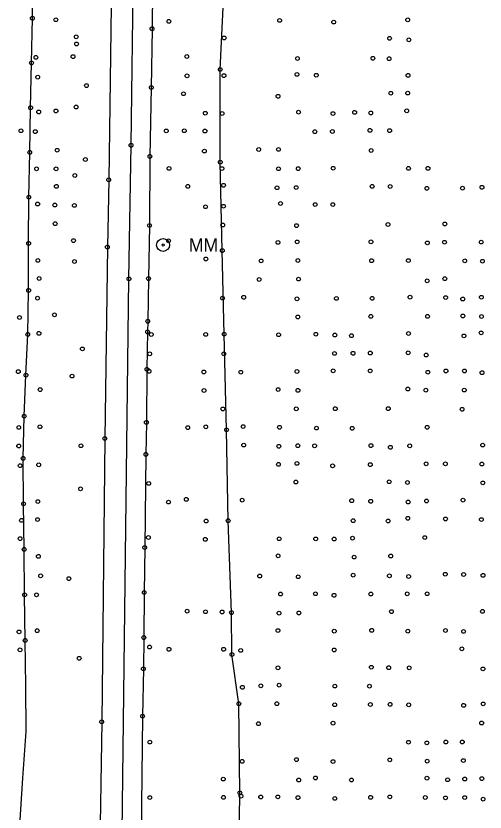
# Model space of a CAD drawing. Extents: x 20503438 to 20508873, y 7964251 to 7984667.
# Drawn here: x 20506616.9 to 20506866.4, y 7966287.3 to 7966710.9 of the extents above; entities that cross this region are included whole.
import ezdxf

# ---------------------------------------------------------------- set-up
doc = ezdxf.new("R2010")
doc.units = 0
for name, color, linetype in [('SurBreakLine', 7, 'Continuous'), ('SurConcreteSlab', 7, 'Continuous'), ('SurDrainageArrowDown', 7, 'Continuous'), ('SurDrainageArrowUp', 7, 'Continuous'), ('SurEdgeRoadPaved', 7, 'Continuous'), ('SurRoadPoints', 7, 'Continuous'), ('SurSurveyPoints', 7, 'Continuous')]:
    doc.layers.add(name, color=color, linetype=linetype)

msp = doc.modelspace()

# ---------------------------------------------------------------- linework, layer by layer
at = {"layer": 'SurBreakLine'}
msp.add_lwpolyline([(20506676.27, 7967436.58), (20506673.75, 7967260.63), (20506673.38, 7967229.74), (20506672.93, 7967188.92), (20506672.41, 7967153.72), (20506672.19, 7967124.04), (20506671.1, 7967048.34), (20506670.26, 7966945.33), (20506669.67, 7966906.46), (20506669.41, 7966871.04), (20506668.85, 7966836.8), (20506668.54, 7966801.73), (20506668.02, 7966767.22), (20506667.76, 7966729.81), (20506666.24, 7966623.69), (20506665.51, 7966587.93), (20506664.19, 7966486.04), (20506662.51, 7966335.32), (20506661.23, 7966248.03), (20506660.03, 7966157.63), (20506658.3, 7966009.76)], dxfattribs=at)
at = {"layer": 'SurConcreteSlab'}
msp.add_lwpolyline([(20506689.7, 7966746.61), (20506689.28, 7966704.08), (20506688.88, 7966672.82), (20506688.14, 7966636.15), (20506687.92, 7966599.43), (20506687.39, 7966571.12), (20506686.99, 7966548.42), (20506686.9, 7966542.73), (20506686.59, 7966522.86), (20506686.25, 7966494.65), (20506686.03, 7966477.61), (20506685.38, 7966428.04), (20506685.13, 7966404.1), (20506684.93, 7966380.11), (20506684.65, 7966363.47), (20506684.25, 7966338.35), (20506682.89, 7966227.64), (20506681.53, 7966131.86)], dxfattribs=at)
at = {"layer": 'SurDrainageArrowDown'}
msp.add_lwpolyline([(20506616.88, 7966180.41), (20506617.4, 7966205.4), (20506617.92, 7966230.4), (20506618.45, 7966255.39), (20506618.97, 7966280.39), (20506620.54, 7966305.33), (20506622.35, 7966330.27), (20506622.07, 7966354.47), (20506621.79, 7966378.67), (20506621.52, 7966402.88), (20506621.24, 7966427.08), (20506620.96, 7966451.29), (20506620.68, 7966475.49), (20506621.28, 7966497.96), (20506622.23, 7966519.72), (20506623.18, 7966541.47), (20506623.65, 7966564.87), (20506623.65, 7966589.87), (20506623.79, 7966614.5), (20506624.24, 7966638.28), (20506624.7, 7966662.06), (20506625.16, 7966685.84), (20506625.61, 7966709.62), (20506625.94, 7966733.94)], dxfattribs=at)
at = {"layer": 'SurDrainageArrowUp'}
msp.add_lwpolyline([(20506748.37, 7966102.43), (20506739.98, 7966120.94), (20506735.03, 7966132), (20506735.65, 7966158.21), (20506738.35, 7966207.5), (20506735.41, 7966256.62), (20506736, 7966297.52), (20506735.47, 7966344.97), (20506731.78, 7966371.15), (20506731.51, 7966393.42), (20506729.75, 7966442.32), (20506728.92, 7966490.67), (20506727.65, 7966541.52), (20506726.65, 7966586.02), (20506725.58, 7966633.07), (20506725.56, 7966682.41), (20506728.02, 7966733.71)], dxfattribs=at)
at = {"layer": 'SurEdgeRoadPaved'}
msp.add_lwpolyline([(20506671.44, 7966131.99), (20506673.27, 7966261.84), (20506677.01, 7966570.96), (20506678.1, 7966642.03), (20506680.7, 7966833.13), (20506681.3, 7966886.9), (20506681.36, 7966892.52), (20506681.4, 7966895.33), (20506681.63, 7966918.21), (20506682.1, 7966969.83), (20506684.74, 7967192.21), (20506685.18, 7967235.97), (20506685.47, 7967264.79), (20506686.29, 7967317.73), (20506686.56, 7967334.59), (20506686.95, 7967373.78)], dxfattribs=at)
at = {"layer": 'SurRoadPoints'}
for radius in [3.43, 0.571]:
    msp.add_circle((20506695.16, 7966588.99), radius, dxfattribs=at)
at = {"layer": 'SurSurveyPoints'}
for centre in [(20506625.61, 7966709.62), (20506638.1, 7966708.83), (20506757.15, 7966708.48), (20506825.26, 7966708.81), (20506689.28, 7966704.08), (20506698.26, 7966707.98), (20506785.91, 7966707.6), (20506648.97, 7966699.76), (20506649.15, 7966695.97), (20506727.64, 7966699.16), (20506815.62, 7966698.95), (20506825.9, 7966698.17), (20506627.51, 7966688.83), (20506647.26, 7966689.2), (20506707.77, 7966689.27), (20506766.6, 7966688.2), (20506806.76, 7966688.32), (20506815.37, 7966688.11), (20506625.16, 7966685.84), (20506707.89, 7966679.02), (20506725.56, 7966682.41), (20506727.53, 7966679.11), (20506766.36, 7966679.76), (20506776.65, 7966679.32), (20506825.44, 7966679.26), (20506628.47, 7966678.28), (20506654.38, 7966673.8), (20506688.88, 7966672.82), (20506706.02, 7966669.47), (20506756.28, 7966668.12), (20506816.25, 7966669.74), (20506825.27, 7966669.83), (20506624.7, 7966662.06), (20506648.87, 7966662.39), (20506628.99, 7966659.78), (20506638.19, 7966660.3), (20506717.61, 7966659.09), (20506726.62, 7966658.97), (20506767.21, 7966659.68), (20506785.5, 7966658.92), (20506797.05, 7966659.55), (20506805.61, 7966659.26), (20506824.73, 7966660.39), (20506619.57, 7966649.77), (20506627.17, 7966649.32), (20506696.85, 7966649.7), (20506706.45, 7966649.78), (20506717.44, 7966649.63), (20506775.89, 7966649.28), (20506785.18, 7966649.39), (20506805.2, 7966649.99), (20506815.67, 7966649.84), (20506678.1, 7966642.03), (20506624.24, 7966638.28), (20506638.82, 7966639.42), (20506717.11, 7966638.95), (20506746.01, 7966639.83), (20506756.53, 7966639.84), (20506805.8, 7966639.27), (20506653.82, 7966634.5), (20506688.14, 7966636.15), (20506725.58, 7966633.07), (20506627.87, 7966629.52), (20506638.23, 7966629.54), (20506698.33, 7966629.73), (20506726.46, 7966629.66), (20506756.56, 7966629.57), (20506767.04, 7966629.64), (20506785.6, 7966629.83), (20506825.68, 7966629.78), (20506836.04, 7966629.77), (20506648.22, 7966625.98), (20506666.24, 7966623.69), (20506638.39, 7966620.18), (20506708.28, 7966620.18), (20506727.32, 7966620.78), (20506755.75, 7966619.46), (20506765.93, 7966619.54), (20506806.34, 7966620.18), (20506815.96, 7966620.12), (20506864.78, 7966619.71), (20506835.49, 7966619.15), (20506854.42, 7966619.22), (20506623.79, 7966614.5), (20506757.6, 7966611.08), (20506628.43, 7966610.79), (20506637.55, 7966610.28), (20506647.95, 7966610.05), (20506717.76, 7966609.36), (20506727.33, 7966609.62), (20506776.06, 7966610.51), (20506785.43, 7966610.52), (20506637.77, 7966600.32), (20506687.92, 7966599.43), (20506726.89, 7966599.61), (20506766.16, 7966599.31), (20506814.76, 7966599.93), (20506845, 7966600.2), (20506623.65, 7966589.87), (20506647.48, 7966591.34), (20506698.06, 7966591.2), (20506756.27, 7966590.36), (20506766.45, 7966590.66), (20506805.74, 7966590.71), (20506835.74, 7966590.11), (20506844.83, 7966590.48), (20506864.38, 7966590.55), (20506665.51, 7966587.93), (20506726.65, 7966586.02), (20506717.92, 7966581.59), (20506628.57, 7966580.8), (20506647.99, 7966580.23), (20506747.27, 7966580.54), (20506766.86, 7966580.75), (20506806.07, 7966580.64), (20506825.63, 7966580.73), (20506855.61, 7966580.56), (20506865.01, 7966580.35), (20506629.19, 7966571.18), (20506677.01, 7966570.96), (20506687.39, 7966571.12), (20506746.25, 7966570.67), (20506767.22, 7966570.86), (20506835.65, 7966569.96), (20506845.01, 7966571.07), (20506623.65, 7966564.87), (20506628.39, 7966560.74), (20506726.79, 7966560.76), (20506738.03, 7966561.17), (20506766.37, 7966560.34), (20506787.33, 7966560.57), (20506806.33, 7966560.63), (20506826.49, 7966561.25), (20506845.46, 7966561.03), (20506854.53, 7966560.25), (20506864.44, 7966561.2), (20506637.37, 7966551.83), (20506618.77, 7966550.44), (20506686.99, 7966548.42), (20506766.8, 7966550.73), (20506805.66, 7966551.02), (20506835.83, 7966551.02), (20506854.58, 7966551.24), (20506864.57, 7966550.95), (20506623.18, 7966541.47), (20506629.14, 7966541.98), (20506686.9, 7966542.73), (20506688.9, 7966541.37), (20506717.82, 7966541.43), (20506727.65, 7966541.52), (20506756.62, 7966541.25), (20506776.44, 7966541.52), (20506786.5, 7966541.1), (20506795.34, 7966540.74), (20506825.7, 7966541.91), (20506855.19, 7966540.65), (20506864.35, 7966542.24), (20506652.22, 7966533.72), (20506688.05, 7966531.11), (20506727.47, 7966531.09), (20506786.35, 7966531.31), (20506796.2, 7966531.4), (20506805.36, 7966531.53), (20506825.5, 7966531.65), (20506835.13, 7966530.47), (20506686.59, 7966522.86), (20506785.6, 7966522.04), (20506805.28, 7966522.03), (20506845.63, 7966521.98), (20506855.45, 7966522), (20506618.15, 7966521.63), (20506622.23, 7966519.72), (20506646.74, 7966519.25), (20506687.7, 7966521.8), (20506716.84, 7966521.46), (20506736.48, 7966521.32), (20506766.35, 7966521.69), (20506835.97, 7966521.3), (20506864.81, 7966521.08), (20506629.79, 7966512.05), (20506716.92, 7966511.62), (20506756.34, 7966512.1), (20506766.9, 7966511.66), (20506825.32, 7966512.39), (20506834.89, 7966511.78), (20506855.38, 7966511.82), (20506726.93, 7966501.78), (20506766.02, 7966501.84), (20506786.75, 7966501.92), (20506814.95, 7966501.96), (20506854.21, 7966501.59), (20506621.28, 7966497.96), (20506629.67, 7966492.32), (20506686.25, 7966494.65), (20506717.84, 7966492.26), (20506737.71, 7966492.41), (20506618.39, 7966491.94), (20506708.28, 7966491.83), (20506728.92, 7966490.67), (20506757.07, 7966492.01), (20506776.71, 7966491.59), (20506795.77, 7966491.5), (20506835.64, 7966492.01), (20506664.19, 7966486.04), (20506618.37, 7966482.07), (20506651.48, 7966482.21), (20506738.04, 7966482.56), (20506756.72, 7966481.9), (20506766.83, 7966482.24), (20506775.75, 7966482.15), (20506805.72, 7966482.26), (20506816.04, 7966481.37), (20506826.33, 7966482.17), (20506865.14, 7966482.56), (20506620.68, 7966475.49), (20506686.03, 7966477.61), (20506619.11, 7966471.61), (20506628.98, 7966472.04), (20506756.49, 7966472.29), (20506766.37, 7966472.81), (20506785.35, 7966471.54), (20506805.38, 7966472.17), (20506835.06, 7966472.59), (20506845.3, 7966472.6), (20506864.68, 7966472.48), (20506765.8, 7966462.89), (20506815.43, 7966463.05), (20506825.12, 7966462.64), (20506651.26, 7966459.26), (20506687.51, 7966462.15), (20506865.25, 7966462.43), (20506620.96, 7966451.29), (20506628.57, 7966452.52), (20506698.05, 7966452.22), (20506707.49, 7966453.69), (20506737.26, 7966453.25), (20506795.49, 7966452.97), (20506805.57, 7966452.65), (20506825.53, 7966452.25), (20506835.29, 7966452.81), (20506854.68, 7966453.24), (20506619.86, 7966442.52), (20506628.39, 7966442.92), (20506718.07, 7966442.15), (20506729.75, 7966442.32), (20506796.25, 7966442.34), (20506814.83, 7966442.17), (20506825.3, 7966443.62), (20506845.39, 7966443.25), (20506864.44, 7966442.92), (20506687.31, 7966433.38), (20506795.94, 7966433.03), (20506834.33, 7966433.34), (20506619.11, 7966432.79), (20506717.61, 7966432.4), (20506756.88, 7966432.72), (20506776.33, 7966432.64), (20506786.15, 7966432.58), (20506621.24, 7966427.08), (20506685.38, 7966428.04), (20506628.83, 7966423.35), (20506756.32, 7966423.63), (20506796.75, 7966422.96), (20506816.23, 7966423.52), (20506630.03, 7966412.98), (20506746.54, 7966412.89), (20506767.04, 7966412.5), (20506796.27, 7966413.36), (20506815.51, 7966413.01), (20506825.75, 7966412.66), (20506845.26, 7966413.85), (20506855.03, 7966413.7), (20506865.32, 7966413.26), (20506645.05, 7966411.52), (20506685.13, 7966404.1), (20506757.66, 7966403.33), (20506776.19, 7966403.47), (20506805.66, 7966403.31), (20506825.02, 7966403.42), (20506835.59, 7966403.45), (20506621.52, 7966402.88), (20506627.86, 7966402.91), (20506786.08, 7966402.64), (20506707.91, 7966394.22), (20506717.71, 7966393.88), (20506726.55, 7966393.79), (20506731.51, 7966393.42), (20506756.83, 7966393.13), (20506767.4, 7966393.25), (20506816.61, 7966393.96), (20506865.02, 7966394.09), (20506618.54, 7966383.16), (20506628.22, 7966383.81), (20506756.26, 7966383.87), (20506786.21, 7966383.55), (20506806.11, 7966383.98), (20506825.29, 7966383.58), (20506845.32, 7966383.91), (20506854.97, 7966383.41), (20506621.79, 7966378.67), (20506684.93, 7966380.11), (20506619.05, 7966373.62), (20506687.97, 7966375.11), (20506698.29, 7966373.93), (20506727.37, 7966373.93), (20506854.09, 7966374.17), (20506731.78, 7966371.15), (20506736.44, 7966373.31), (20506786.2, 7966373.56), (20506650.53, 7966369.13), (20506684.65, 7966363.47), (20506756.26, 7966364.06), (20506805.92, 7966364.37), (20506815.16, 7966364.13), (20506826.07, 7966364.04), (20506865.29, 7966363.49), (20506737.32, 7966353.69), (20506747.17, 7966354.48), (20506756.86, 7966354.83), (20506786.49, 7966354.34), (20506804.9, 7966354.29), (20506735.47, 7966344.97), (20506755.64, 7966344.96), (20506786.44, 7966344.41), (20506805.4, 7966344.56), (20506815.91, 7966344.63), (20506825.79, 7966344.35), (20506855.01, 7966344.1), (20506865.42, 7966344.87), (20506684.25, 7966338.35), (20506662.51, 7966335.32), (20506745.88, 7966334.33), (20506785.56, 7966334.62), (20506864.59, 7966334.68), (20506688.13, 7966324.54), (20506825.69, 7966324.48), (20506835.46, 7966324.11), (20506845.53, 7966324.57), (20506854.32, 7966324.6), (20506766.07, 7966315.21), (20506815.73, 7966315.07), (20506835.67, 7966314.42), (20506854.89, 7966314.72), (20506737.19, 7966314.3), (20506785.55, 7966314.19), (20506727.18, 7966304.86), (20506767.29, 7966304.36), (20506776.18, 7966305.48), (20506795.32, 7966304.38), (20506835.5, 7966305.36), (20506846.5, 7966304.5), (20506855.57, 7966304.89), (20506864.69, 7966305.11), (20506736, 7966297.52), (20506688.09, 7966295.04), (20506727.25, 7966295.13), (20506736.6, 7966295.76), (20506747.06, 7966295.34), (20506756.2, 7966295.39), (20506766.91, 7966294.99), (20506786.53, 7966294.57), (20506805.54, 7966295.13), (20506815.77, 7966295.39), (20506834.61, 7966295.09), (20506845.35, 7966294.87), (20506855.58, 7966295.02), (20506865.36, 7966294.19)]:
    msp.add_circle(centre, 1, dxfattribs=at)

# ---------------------------------------------------------------- texts
at = {"layer": 'SurRoadPoints'}
msp.add_text('MM', height=6.995, rotation=360, dxfattribs=at).set_placement((20506708.87, 7966585.49))

doc.saveas('drawing.dxf')
